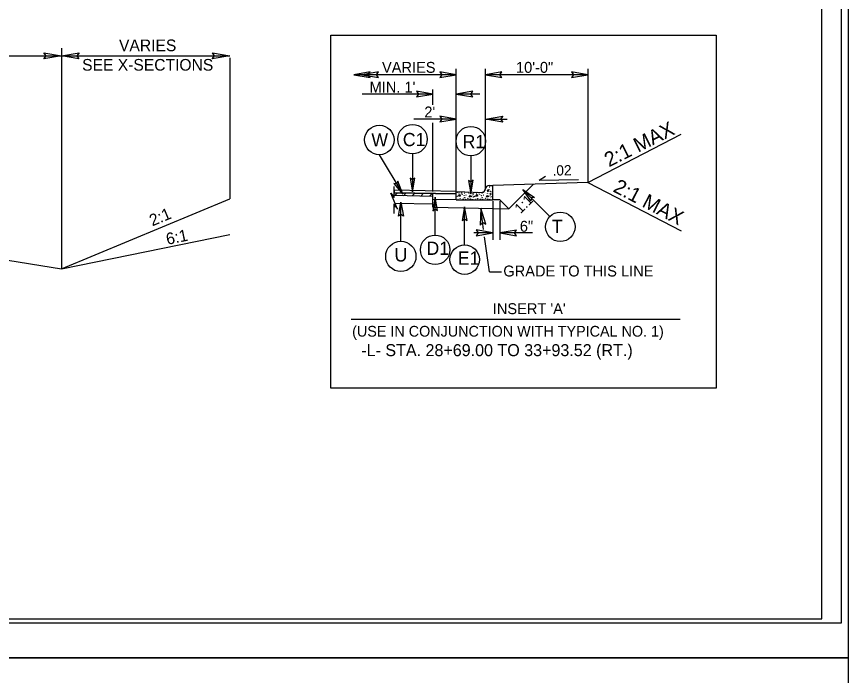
# Model space of a CAD drawing. Extents: x 981824 to 982276, y 44828 to 45204.
# Drawn here: x 982186.38 to 982229.08, y 45089.07 to 45122.91 of the extents above; entities that cross this region are included whole.
import ezdxf

# ---------------------------------------------------------------- set-up
doc = ezdxf.new("R2010")
doc.units = 0
for name, color, linetype in [('Old_Level_1', 7, 'Continuous'), ('Old_Level_11', 7, 'Continuous'), ('Old_Level_18', 7, 'Continuous'), ('Old_Level_2', 7, 'Continuous'), ('Old_Level_20', 7, 'Continuous'), ('Old_Level_3', 7, 'Continuous'), ('Old_Level_50', 7, 'Continuous'), ('Old_Level_51', 7, 'Continuous'), ('Prop Dimension Text', 7, 'Continuous'), ('Typical Terminator CELL', 7, 'Continuous')]:
    doc.layers.add(name, color=color, linetype=linetype)

msp = doc.modelspace()

# ---------------------------------------------------------------- linework, layer by layer
at = {"layer": 'Old_Level_1'}
for p, q in [((982188.683, 45121.294), (982188.683, 45109.944)), ((982179.083, 45120.894), (982188.683, 45120.894)), ((982188.683, 45120.894), (982197.333, 45120.894)), ((982197.333, 45120.798), (982197.333, 45113.542)), ((982208.953, 45113.923), (982208.953, 45120.231)), ((982210.448, 45114.059), (982210.448, 45120.231)), ((982208.953, 45119.925), (982203.688, 45119.925)), ((982215.713, 45119.925), (982210.448, 45119.925)), ((982207.751, 45118.371), (982207.751, 45119.16)), ((982207.751, 45118.932), (982204.112, 45118.932)), ((982210.157, 45118.932), (982208.953, 45118.932)), ((982208.953, 45117.643), (982206.768, 45117.643)), ((982207.751, 45113.923), (982207.751, 45117.459)), ((982210.448, 45117.643), (982211.56, 45117.643)), ((982215.713, 45114.388), (982220.494, 45116.873)), ((982205.766, 45113.987), (982205.763, 45113.862)), ((982210.635, 45114.237), (982210.822, 45114.237)), ((982210.822, 45113.489), (982210.822, 45114.237)), ((982215.713, 45114.388), (982220.494, 45111.903)), ((982207.75, 45113.675), (982205.763, 45113.715)), ((982205.796, 45113.714), (982205.941, 45113.859)), ((982206.24, 45113.706), (982206.385, 45113.85)), ((982206.683, 45113.697), (982206.828, 45113.841)), ((982207.127, 45113.688), (982207.272, 45113.832)), ((982207.57, 45113.679), (982207.715, 45113.823)), ((982207.751, 45113.117), (982207.751, 45113.823)), ((982208.953, 45113.923), (982210.256, 45113.881)), ((982208.953, 45113.489), (982208.953, 45113.923)), ((982188.683, 45109.944), (982197.333, 45113.542)), ((982205.767, 45113.157), (982205.853, 45113.155)), ((982207.75, 45113.272), (982205.82, 45113.311)), ((982207.751, 45113.117), (982211.646, 45113.039)), ((982208.953, 45113.489), (982210.822, 45113.489)), ((982210.822, 45113.421), (982210.822, 45111.446)), ((982211.195, 45113.489), (982211.646, 45113.039)), ((982211.195, 45113.421), (982211.195, 45111.446)), ((982210.356, 45111.979), (982210.208, 45113.068)), ((982179.083, 45111.54), (982188.683, 45109.944)), ((982188.683, 45109.944), (982197.333, 45111.711)), ((982210.822, 45111.801), (982209.847, 45111.801)), ((982210.651, 45109.794), (982210.408, 45111.595)), ((982212.868, 45111.801), (982211.195, 45111.801)), ((982210.651, 45109.794), (982211.274, 45109.794))]:
    msp.add_line(p, q, dxfattribs=at)
for points in [[(982205.761, 45112.787), (982205.761, 45113.299), (982205.941, 45113.019), (982205.599, 45113.842), (982205.763, 45113.623), (982205.764, 45114.189)], [(982205.763, 45113.862), (982208.95, 45113.799), (982208.953, 45113.923), (982205.766, 45113.987)]]:
    msp.add_lwpolyline(points, dxfattribs=at)
for centre, start, end in [((982210.261, 45114.068), 268.1716, 357.2429), ((982210.635, 45114.05), 90, 177.2429)]:
    msp.add_arc(centre, 0.187, start, end, dxfattribs=at)
at = {"layer": 'Old_Level_11'}
for p, q in [((982206.705, 45115.858), (982206.705, 45113.902)), ((982209.699, 45115.753), (982209.699, 45113.797)), ((982213.758, 45112.645), (982212.374, 45114.028)), ((982207.869, 45111.686), (982207.869, 45113.642)), ((982209.382, 45111.184), (982209.382, 45113.14))]:
    msp.add_line(p, q, dxfattribs=at)
for points in [[(982202.505, 45121.961), (982222.293, 45121.961), (982222.293, 45103.817), (982202.505, 45103.817)], [(982204.529, 45120.07), (982203.688, 45119.925), (982204.534, 45119.775), (982204.426, 45119.925)], [(982204.953, 45120.066), (982204.112, 45119.922), (982204.958, 45119.772), (982204.85, 45119.922)], [(982208.112, 45119.78), (982208.953, 45119.925), (982208.107, 45120.074), (982208.215, 45119.925)], [(982211.289, 45120.07), (982210.448, 45119.925), (982211.294, 45119.775), (982211.186, 45119.925)], [(982214.872, 45119.78), (982215.713, 45119.925), (982214.867, 45120.074), (982214.975, 45119.925)], [(982206.91, 45118.787), (982207.751, 45118.932), (982206.905, 45119.081), (982207.012, 45118.932)], [(982209.794, 45119.077), (982208.953, 45118.932), (982209.798, 45118.782), (982209.691, 45118.932)], [(982208.112, 45117.498), (982208.953, 45117.643), (982208.107, 45117.793), (982208.215, 45117.643)], [(982205.745, 45114.334), (982206.208, 45113.794), (982205.953, 45114.463), (982205.892, 45114.322)], [(982206.584, 45114.602), (982206.705, 45113.902), (982206.829, 45114.606), (982206.705, 45114.517)], [(982209.578, 45114.498), (982209.699, 45113.797), (982209.823, 45114.502), (982209.699, 45114.412)], [(982212.784, 45113.447), (982212.374, 45114.028), (982212.96, 45113.618), (982212.809, 45113.594)], [(982207.99, 45112.942), (982207.869, 45113.642), (982207.744, 45112.938), (982207.869, 45113.027)], [(982205.982, 45112.659), (982206.106, 45113.379), (982206.234, 45112.655), (982206.106, 45112.747)], [(982209.503, 45112.439), (982209.382, 45113.14), (982209.258, 45112.435), (982209.382, 45112.525)], [(982210.466, 45112.247), (982210.209, 45113.061), (982210.175, 45112.203), (982210.308, 45112.33)], [(982209.981, 45111.656), (982210.822, 45111.801), (982209.976, 45111.951), (982210.083, 45111.801)], [(982212.036, 45111.946), (982211.195, 45111.801), (982212.041, 45111.652), (982211.934, 45111.801)]]:
    msp.add_lwpolyline(points, close=True, dxfattribs=at)
msp.add_lwpolyline([(982204.996, 45115.816), (982206.208, 45113.794)], dxfattribs=at)
for centre in [(982205.005, 45116.573), (982206.705, 45116.614), (982209.699, 45116.51), (982214.292, 45112.11), (982207.869, 45110.93), (982209.382, 45110.427)]:
    msp.add_circle(centre, 0.757, dxfattribs=at)
at = {"layer": 'Old_Level_18'}
msp.add_lwpolyline([(982227.72, 45175.969), (982107.72, 45175.969), (982107.72, 45091.969), (982227.72, 45091.969)], close=True, dxfattribs=at)
at = {"layer": 'Old_Level_2'}
for p, q in [((982215.713, 45120.231), (982215.713, 45114.388)), ((982213.201, 45114.505), (982213.54, 45114.71)), ((982213.201, 45114.505), (982215.218, 45114.545)), ((982210.535, 45113.985), (982210.547, 45113.92)), ((982210.646, 45113.953), (982210.535, 45113.985)), ((982209.065, 45113.678), (982209.127, 45113.764)), ((982209.152, 45113.683), (982209.065, 45113.678)), ((982209.127, 45113.764), (982209.152, 45113.683)), ((982209.614, 45113.642), (982209.659, 45113.724)), ((982209.733, 45113.67), (982209.614, 45113.642)), ((982209.659, 45113.724), (982209.733, 45113.67)), ((982209.962, 45113.678), (982210.023, 45113.764)), ((982210.048, 45113.683), (982209.962, 45113.678)), ((982210.023, 45113.764), (982210.048, 45113.683)), ((982210.511, 45113.642), (982210.556, 45113.724)), ((982210.63, 45113.67), (982210.511, 45113.642)), ((982210.547, 45113.92), (982210.646, 45113.953)), ((982210.556, 45113.724), (982210.63, 45113.67))]:
    msp.add_line(p, q, dxfattribs=at)
for centre in [(982210.433, 45114.035), (982210.507, 45114.17), (982210.626, 45114.014), (982210.662, 45114.145), (982210.793, 45114.096), (982209, 45113.679), (982209.02, 45113.883), (982209.09, 45113.822), (982209.123, 45113.895), (982209.151, 45113.56), (982209.229, 45113.85), (982209.25, 45113.777), (982209.299, 45113.544), (982209.356, 45113.716), (982209.377, 45113.839), (982209.381, 45113.605), (982209.389, 45113.875), (982209.446, 45113.736), (982209.549, 45113.568), (982209.573, 45113.854), (982209.659, 45113.818), (982209.672, 45113.54), (982209.786, 45113.749), (982209.799, 45113.818), (982209.827, 45113.646), (982209.839, 45113.794), (982209.896, 45113.679), (982209.917, 45113.883), (982209.986, 45113.822), (982210.048, 45113.56), (982210.126, 45113.85), (982210.146, 45113.777), (982210.195, 45113.544), (982210.253, 45113.716), (982210.273, 45113.839), (982210.277, 45113.605), (982210.285, 45113.875), (982210.343, 45113.736), (982210.445, 45113.568), (982210.47, 45113.854), (982210.556, 45113.818), (982210.568, 45113.54), (982210.683, 45113.749), (982210.695, 45113.818), (982210.72, 45113.936), (982210.724, 45113.646), (982210.735, 45113.794), (982210.793, 45113.679), (982210.813, 45113.883), (982209.037, 45113.511), (982209.422, 45113.523), (982209.782, 45113.527), (982209.933, 45113.511), (982210.318, 45113.523), (982210.679, 45113.527), (982210.83, 45113.511)]:
    msp.add_circle(centre, 0.00576, dxfattribs=at)
msp.add_arc((982210.019, 45113.895), 0.00576, 170.8368, 4.3878, dxfattribs=at)
at = {"layer": 'Old_Level_3'}
for p, q in [((982208.953, 45113.923), (982205.764, 45113.987)), ((982215.713, 45114.388), (982210.822, 45114.237)), ((982211.646, 45113.039), (982212.908, 45114.301)), ((982208.952, 45113.799), (982205.763, 45113.862)), ((982208.945, 45113.489), (982207.751, 45113.513)), ((982211.195, 45113.489), (982210.822, 45113.489)), ((982220.45, 45107.347), (982203.55, 45107.347))]:
    msp.add_line(p, q, dxfattribs=at)
at = {"layer": 'Old_Level_50'}
msp.add_line((982229.08, 45089.969), (982229.08, 45089.969), dxfattribs=at)
msp.add_lwpolyline([(982228.72, 45176.173), (982095.4, 45176.173), (982095.4, 45091.765), (982228.72, 45091.765)], close=True, dxfattribs=at)
at = {"layer": 'Old_Level_51'}
for points in [[(982229.08, 45177.969), (982094.36, 45177.969), (982094.36, 45089.969), (982229.08, 45089.969)], [(982229.08, 45089.969), (982094.36, 45089.969), (982094.36, 45001.969), (982229.08, 45001.969)]]:
    msp.add_lwpolyline(points, close=True, dxfattribs=at)
at = {"layer": 'Prop Dimension Text'}
msp.add_line((982206.106, 45111.369), (982206.106, 45113.379), dxfattribs=at)
msp.add_circle((982206.105, 45110.591), 0.778, dxfattribs=at)
at = {"layer": 'Typical Terminator CELL'}
for points in [[(982187.783, 45121.049), (982188.683, 45120.894), (982187.778, 45120.734), (982187.893, 45120.894)], [(982189.583, 45120.739), (982188.683, 45120.894), (982189.588, 45121.054), (982189.473, 45120.894)], [(982196.433, 45121.049), (982197.333, 45120.894), (982196.428, 45120.734), (982196.543, 45120.894)], [(982211.337, 45117.49), (982210.448, 45117.643), (982211.342, 45117.801), (982211.228, 45117.643)]]:
    msp.add_lwpolyline(points, close=True, dxfattribs=at)

# ---------------------------------------------------------------- texts
at = {"layer": 'Old_Level_1'}
for s, height, rotation, p in [('VARIES', 0.5606, 360, (982205.137, 45120.02)), ('10\'-0"', 0.5606, 360, (982212.018, 45120.02)), ("MIN. 1'", 0.5606, 360, (982204.501, 45119.005)), ("2'", 0.5606, 360, (982207.311, 45117.729)), ('2:1 MAX', 0.75, 26.5646, (982216.79, 45115.163)), ('.02', 0.5232, 1.1458, (982213.899, 45114.74)), ('2:1 MAX', 0.75, 332.6161, (982216.955, 45113.941)), ('2:1', 0.6, 22.5828, (982193.347, 45112.131)), ('6"', 0.5606, 360, (982212.215, 45111.858)), ('6:1', 0.6, 11.5396, (982194.119, 45111.182))]:
    msp.add_text(s, height=height, rotation=rotation, dxfattribs=at).set_placement(p)
at = {"layer": 'Old_Level_20'}
for s, height, p in [('W', 0.677, (982204.594, 45116.236)), ('C1', 0.6774, (982206.207, 45116.254)), ('R1', 0.6774, (982209.276, 45116.15)), ('T ', 0.6774, (982213.862, 45111.798)), ('D1', 0.6774, (982207.423, 45110.67)), ('E1', 0.6774, (982209.028, 45110.168))]:
    msp.add_text(s, height=height, rotation=360, dxfattribs=at).set_placement(p)
msp.add_text('U', height=0.696, dxfattribs=at).set_placement((982205.775, 45110.327))
at = {"layer": 'Old_Level_3'}
for s, height, rotation, p in [('1:1', 0.5233, 45, (982212.254, 45112.757)), ('GRADE TO THIS LINE', 0.56063, 360, (982211.367, 45109.559))]:
    msp.add_text(s, height=height, rotation=rotation, dxfattribs=at).set_placement(p)
for s, height, p in [("INSERT 'A'", 0.5606, (982210.825, 45107.626)), ('(USE IN CONJUNCTION WITH TYPICAL NO. 1)', 0.55074, (982203.606, 45106.471)), ('-L- STA. 28+69.00 TO 33+93.52 (RT.)', 0.61669, (982204.074, 45105.467))]:
    msp.add_text(s, height=height, dxfattribs=at).set_placement(p)
at = {"layer": 'Prop Dimension Text'}
for s, p in [('VARIES', (982191.637, 45121.131)), ('SEE X-SECTIONS', (982189.744, 45120.131))]:
    msp.add_text(s, height=0.6, dxfattribs=at).set_placement(p)

doc.saveas('drawing.dxf')
